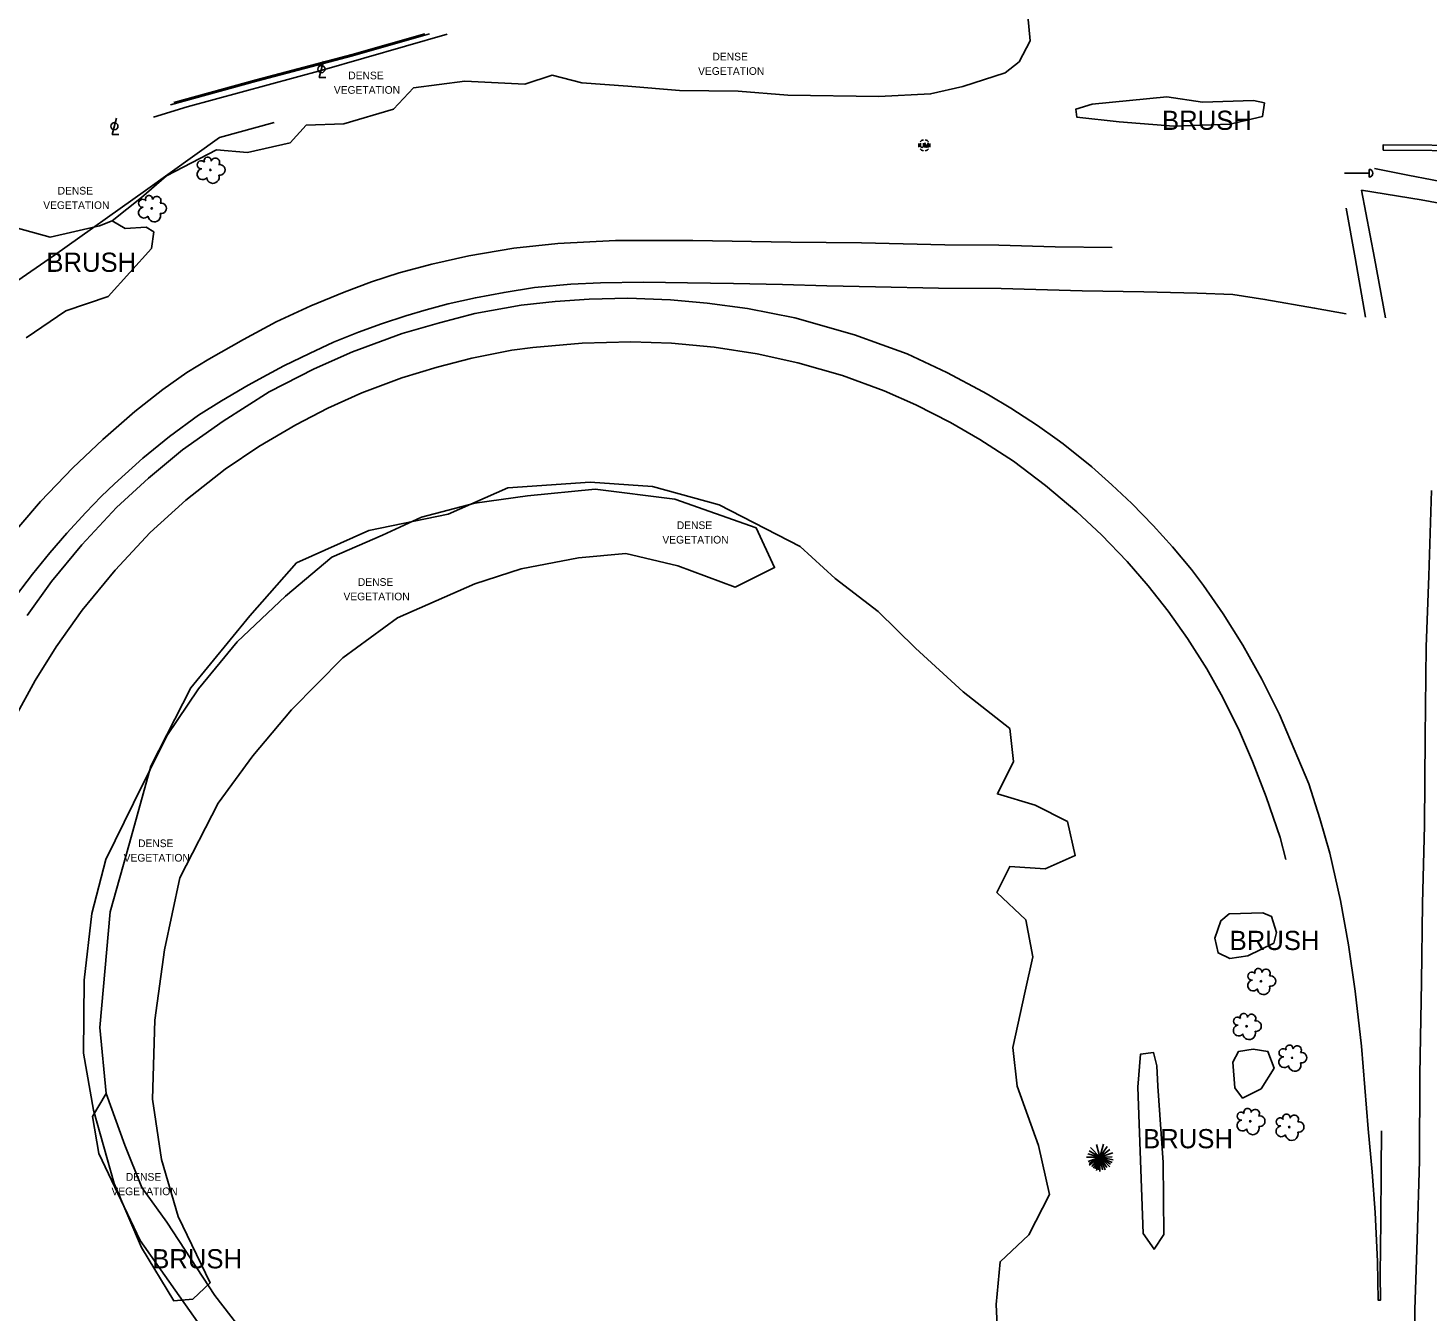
# Model space of a CAD drawing. Extents: x 2129547 to 2134906, y 657330 to 659734.
# Drawn here: x 2131974 to 2132485, y 658719 to 659188 of the extents above; entities that cross this region are included whole.
import ezdxf

# ---------------------------------------------------------------- set-up
doc = ezdxf.new("R2010")
doc.units = 0
for name, color, linetype in [('Default', 7, 'Continuous'), ('LT_X_Poles', 7, 'Continuous'), ('PM_X_Crosswalk2', 7, 'Continuous'), ('PM_X_Edge_Line', 7, 'Continuous'), ('PM_X_Lane_Line', 7, 'Continuous'), ('PM_X_Stop_Line2', 7, 'Continuous'), ('PV_X_Curb', 7, 'Continuous'), ('PV_X_Parking_Lot', 7, 'Continuous'), ('RD_X_Fence', 7, 'Continuous'), ('RD_X_Misc_Items', 7, 'Continuous'), ('SG_X_Detection', 7, 'Continuous'), ('UT_X_Unknown_Cells', 7, 'Continuous'), ('VG_X_Cells', 7, 'Continuous'), ('VG_X_Shrub_Line_Lt', 7, 'Continuous'), ('VG_X_Text', 7, 'Continuous'), ('VG_X_Tree_Line_Lt', 7, 'Continuous')]:
    doc.layers.add(name, color=color, linetype=linetype)

# ---------------------------------------------------------------- blocks, each defined once
blk = doc.blocks.new('LPOLE')
at = {"layer": 'LT_X_Poles'}
blk.add_lwpolyline([(0.01, 0.0375), (-0.01, -0.0385), (0.02, -0.0385)], dxfattribs=at)
blk.add_circle((0, 0), 0.0165, dxfattribs=at)
blk = doc.blocks.new('TREE')
at = {"layer": 'VG_X_Cells'}
blk.add_circle((0, 0), 0.00305, dxfattribs=at)
for centre, radius, start, end in [((-0.0362, -0.0197), 0.0251, 96.17219, 320.57371), ((-0.042, 0.0237), 0.0187, 39.06254, 279.54124), ((-0.0125, 0.0428), 0.0167, 354.0047, 205.97412), ((0.0232, 0.0359), 0.0197, 323.82996, 165.0376), ((0.0439, 0.0005), 0.0243, 259.14531, 101.45961), ((0.012, -0.0331), 0.029, 184.94757, 19.45715)]:
    blk.add_arc(centre, radius, start, end, dxfattribs=at)
blk = doc.blocks.new('UMH')
at = {"layer": 'UT_X_Unknown_Cells'}
for p, q in [((-0.017, 0.0104), (-0.017, -0.0059)), ((-0.0042, 0.0104), (-0.0042, -0.0059))]:
    blk.add_line(p, q, dxfattribs=at)
blk.add_lwpolyline([(0.0024, -0.01), (0.0024, 0.0104), (0.0099, -0.01), (0.0174, 0.0104), (0.0174, -0.01)], dxfattribs=at)
for centre, radius, start, end in [((0, 0), 0.0254, 160.01689, 200.03919), ((0, 0), 0.0254, 100.0806, 140.07213), ((0, 0), 0.0254, 40.05767, 80.10608), ((0, 0), 0.0254, 340.01689, 20.03919), ((0, 0), 0.0254, 220.05767, 260.04731), ((-0.0106, -0.0029), 0.00708, 205.19243, 334.80757), ((0, 0), 0.0254, 280.01144, 320.02638)]:
    blk.add_arc(centre, radius, start, end, dxfattribs=at)
blk = doc.blocks.new('ETREE')
at = {"layer": 'VG_X_Cells'}
for p, q in [((-0.0627, 0), (0, 0)), ((0, 0), (-0.056, 0.015)), ((0, 0), (-0.0545, -0.0198)), ((0, 0), (-0.0506, -0.029)), ((0, 0), (-0.0496, 0.0292)), ((0, 0), (-0.0496, -0.038)), ((0, 0), (-0.0443, 0.0443)), ((0, 0), (-0.0374, -0.044)), ((0, 0), (-0.0294, -0.051)), ((0, 0), (-0.0211, -0.0551)), ((0, 0), (-0.016, -0.0617)), ((0, 0), (-0.0157, 0.0586)), ((0, 0), (-0.0069, -0.0583)), ((0, 0), (0.016, 0.0597)), ((0, 0), (0.0337, 0.0493)), ((0, 0), (0.0464, 0.0356)), ((0, 0), (0.0602, 0.0204)), ((0, 0), (0.0573, 0.0012)), ((0, -0.0665), (0, 0)), ((0, 0), (0.0117, -0.0589)), ((0, 0), (0.0246, -0.0593)), ((0, 0), (0.0322, -0.0482)), ((0, 0), (0.0456, -0.0447)), ((0, 0), (0.0485, -0.0324)), ((0, 0), (0.0567, -0.0247)), ((0, 0), (0.0613, -0.0122))]:
    blk.add_line(p, q, dxfattribs=at)
blk = doc.blocks.new('PEDPB')
at = {"layer": 'Default'}
blk.add_line((0.0457, 0), (0, 0), dxfattribs=at)
blk.add_lwpolyline([(0.0457, -0.0071), (0.0457, -0.0071), (0.0457, 0.0071), (0.0457, 0.0071)], dxfattribs=at)
blk.add_arc((0.0457, 0), 0.00711, 270.0002, 89.9998, dxfattribs=at)

msp = doc.modelspace()

# ---------------------------------------------------------------- linework, layer by layer
at = {"layer": 'PM_X_Crosswalk2'}
for points in [[(2132534.55, 659123.31), (2132513.69, 659127.04), (2132495.2, 659130.51), (2132477.48, 659133.95), (2132465.32, 659136.32)], [(2132469.3, 659081.92), (2132465.27, 659103.71), (2132460.59, 659128.44), (2132482.25, 659124.89), (2132507.25, 659120.29), (2132536.23, 659114.67), (2132535.64, 659093.84), (2132534.49, 659067.12), (2132533.02, 659033.77)], [(2132454.94, 659121.92), (2132458.19, 659103.79), (2132462.01, 659082.12)]]:
    msp.add_lwpolyline(points, dxfattribs=at)
at = {"layer": 'PM_X_Edge_Line'}
for points in [[(2132369.6, 659107.5), (2132348.81, 659107.85), (2132328.2, 659108.38), (2132308.55, 659108.54), (2132278.14, 659109.27), (2132252.35, 659109.51), (2132216.6, 659110.05), (2132188.42, 659110.07), (2132167.35, 659109.07), (2132151.39, 659107.31), (2132134.97, 659104.51), (2132121.5, 659101.46), (2132109.53, 659098.26), (2132099.49, 659095.05), (2132089.47, 659091.31), (2132077.32, 659086.26), (2132064.72, 659080.45), (2132052.79, 659074.04), (2132040.05, 659066.77), (2132032.09, 659062.01), (2132023.36, 659055.77), (2132013.14, 659047.72), (2132001.4, 659037.49), (2131990.46, 659027.2), (2131978.75, 659014.89), (2131965.12, 658998.99)], [(2132454.96, 659083.37), (2132443.41, 659085.44), (2132425.31, 659088.59), (2132413.55, 659090.4), (2132400.61, 659090.94), (2132381.16, 659091.35), (2132358.63, 659091.73), (2132329.13, 659092.59), (2132306.24, 659092.74), (2132283.24, 659093.2), (2132265.47, 659093.58), (2132249.29, 659094.08), (2132231.52, 659094.41), (2132214.76, 659094.7), (2132198.61, 659094.91), (2132182.91, 659094.68), (2132172.12, 659094.14), (2132158.86, 659092.97), (2132147.78, 659091.16), (2132137.35, 659089.23), (2132127.37, 659086.96), (2132119.42, 659084.86), (2132111.91, 659082.68), (2132103.12, 659079.77), (2132094.69, 659076.7), (2132085.6, 659072.97), (2132076.79, 659068.94), (2132067.52, 659064.36), (2132061.35, 659061.15), (2132054.49, 659057.39), (2132044.71, 659051.65), (2132036.32, 659046.42), (2132025.72, 659038.58), (2132016, 659030.67), (2132005.66, 659021.4), (2132000.8, 659016.75), (2131995.2, 659010.86), (2131988.33, 659003.31), (2131982.16, 658996.19), (2131975.74, 658988.36), (2131967.68, 658977.75)], [(2131973.8, 658973.32), (2131982.78, 658985.7), (2131993.82, 658999.13), (2132006.37, 659012.69), (2132018.09, 659023.44), (2132030.45, 659033.71), (2132045.3, 659044.23), (2132062.09, 659054.86), (2132078.53, 659063.34), (2132092.46, 659069.49), (2132110.64, 659076.22), (2132124.25, 659080.1), (2132137.15, 659083.43), (2132154.08, 659086.47), (2132166.4, 659087.82), (2132178.85, 659088.68), (2132192.97, 659089.07), (2132208.49, 659088.52), (2132221.86, 659087.29), (2132236.56, 659085.27), (2132253.83, 659081.94), (2132275.64, 659075.71), (2132285.68, 659072.09), (2132294.87, 659068.74), (2132309.27, 659061.96), (2132322.49, 659054.92), (2132324.53, 659053.85), (2132332.64, 659048.95), (2132342.39, 659042.66), (2132349.56, 659037.55), (2132351.76, 659035.88), (2132362.16, 659027.56), (2132369.45, 659020.94), (2132376.71, 659014.23), (2132384.59, 659006.17), (2132391.62, 658998.4), (2132398.53, 658990.09), (2132402.88, 658984.23), (2132410.04, 658973.91), (2132417.25, 658962.45), (2132424.15, 658950.13), (2132430.58, 658937.17), (2132441.3, 658911.91), (2132445.33, 658899.24), (2132448.95, 658886.6), (2132452.85, 658869.37), (2132455.83, 658853.2), (2132458.2, 658836.36), (2132460.51, 658816.27), (2132463.02, 658786.06)], [(2132432.93, 658884.27), (2132430.84, 658892.3), (2132425.75, 658907.16), (2132420.8, 658920.06), (2132415.99, 658931.17), (2132410.01, 658943.38), (2132404.07, 658953.86), (2132397.07, 658964.91), (2132390.02, 658974.87), (2132382.72, 658984.2), (2132375.12, 658993.06), (2132365.71, 659002.73), (2132356.71, 659011.15), (2132345.27, 659020.76), (2132333.57, 659029.6), (2132321.35, 659037.57), (2132310.64, 659043.78), (2132298.01, 659050.21), (2132286.49, 659055.25), (2132271.25, 659060.9), (2132254.99, 659065.48), (2132240.11, 659068.8), (2132224.38, 659071.24), (2132208.88, 659072.63), (2132194.03, 659073.19), (2132176.27, 659072.71), (2132158.33, 659071.06), (2132150.61, 659070.08), (2132136.09, 659067.21), (2132123.35, 659063.95), (2132110.55, 659059.97), (2132095.9, 659054.6), (2132083.55, 659048.95), (2132071.86, 659042.93), (2132058.33, 659034.96), (2132046.08, 659026.69), (2132031.74, 659015.37), (2132018.72, 659003.66), (2132005.89, 658989.84), (2131993.94, 658975.32), (2131984.42, 658961.85), (2131976.72, 658949.61), (2131969.57, 658936.5)], [(2132467.88, 658785.31), (2132467.68, 658771.09), (2132467.55, 658752.47), (2132467.35, 658732.97), (2132467.46, 658723.56), (2132466.66, 658723.56), (2132466.35, 658737.65), (2132465.49, 658755.62), (2132464.46, 658770.41), (2132463.02, 658786.06)]]:
    msp.add_lwpolyline(points, dxfattribs=at)
at = {"layer": 'PM_X_Lane_Line'}
msp.add_lwpolyline([(2132479.46, 658662.15), (2132479.91, 658689.3), (2132480.02, 658720.13), (2132480.79, 658745.78), (2132481.72, 658774.42), (2132481.81, 658805.92), (2132482.47, 658839.62), (2132482.81, 658868.33), (2132483.47, 658896.67), (2132483.79, 658929.03), (2132484.16, 658961.85), (2132485.12, 658987.76), (2132486.03, 659018.91)], dxfattribs=at)
at = {"layer": 'PM_X_Stop_Line2'}
msp.add_lwpolyline([(2132468.48, 659143.04), (2132504.1, 659142.84), (2132504.11, 659144.81), (2132468.49, 659145.01)], close=True, dxfattribs=at)
at = {"layer": 'PV_X_Curb'}
msp.add_lwpolyline([(2132026.18, 659159.57), (2132057.53, 659168.26), (2132092.46, 659177.49), (2132119.79, 659185.24), (2132120.61, 659185.47)], dxfattribs=at)
at = {"layer": 'PV_X_Parking_Lot'}
msp.add_lwpolyline([(2132027.38, 659160.42), (2132057.4, 659168.74), (2132092.33, 659177.97), (2132118.88, 659185.5)], dxfattribs=at)
at = {"layer": 'RD_X_Fence'}
msp.add_lwpolyline([(2132063.89, 659153.18), (2132044.02, 659147.7), (2132017.02, 659128.3), (2131983.81, 659104.8), (2131958.11, 659087.15), (2131928.28, 659065.59), (2131913.76, 659055.03), (2131902.3, 659031.68), (2131886.87, 658999.73), (2131870.43, 658966.66), (2131867.28, 658959.81), (2131866.21, 658956.4), (2131857.66, 658938.59), (2131850.11, 658923.77), (2131835.3, 658892.55), (2131813.09, 658849.05), (2131807.77, 658835.77), (2131787.53, 658792.78), (2131778.55, 658773.77), (2131750.93, 658716), (2131727.2, 658667.49), (2131715.31, 658642.03), (2131710.47, 658636.49)], dxfattribs=at)
at = {"layer": 'RD_X_Misc_Items'}
msp.add_lwpolyline([(2132156.39, 659017.01), (2132137.15, 659014.24), (2132117.7, 659009.15), (2132103.4, 659002.63), (2132084.93, 658994.59), (2132068.05, 658980.35), (2132050.41, 658963.74), (2132036.36, 658946.6), (2132024.81, 658929.44), (2132012.6, 658904.93), (2132002.59, 658884.3), (2131997.41, 658864.6), (2131994.68, 658840.32), (2131994.43, 658813.68), (2131998.06, 658792.85), (2132005.57, 658766.2), (2132015.57, 658742.76), (2132027.39, 658723.32), (2132034.31, 658723.98), (2132040.54, 658729.88), (2132028.98, 658754.06), (2132022.83, 658774.96), (2132019.59, 658796.94), (2132020.42, 658825.77), (2132023.99, 658851.44), (2132029.57, 658877.59), (2132043.46, 658904.87), (2132056.14, 658922.15), (2132070.21, 658938.87), (2132088.99, 658957.9), (2132108.97, 658972.48), (2132137.16, 658984.84), (2132153.98, 658990.4), (2132174.97, 658994.41), (2132192.26, 658995.88), (2132211.15, 658991.41), (2132232.04, 658983.67), (2132246.44, 658990.78), (2132239.74, 659005.26), (2132210.12, 659015.8), (2132181.03, 659019.41)], close=True, dxfattribs=at)
at = {"layer": 'VG_X_Shrub_Line_Lt'}
for points in [[(2132402.58, 659160.61), (2132421.13, 659161.21), (2132425.13, 659160.29), (2132424.42, 659155.28), (2132412.53, 659152.58), (2132392.03, 659151.81), (2132372.11, 659153.44), (2132356.76, 659155.04), (2132356.4, 659158.02), (2132362.26, 659159.87), (2132389.5, 659162.53)], [(2132428.58, 658853.86), (2132419.11, 658849.21), (2132412.56, 658848.27), (2132408.24, 658850.24), (2132407.02, 658855.67), (2132409.24, 658861.98), (2132412.31, 658864.55), (2132424.54, 658864.9), (2132427.72, 658863.51), (2132429.59, 658857.75)], [(2132386.23, 658801.69), (2132388.16, 658773.76), (2132388.4, 658747.51), (2132384.87, 658742.16), (2132380.87, 658747.97), (2132378.95, 658801.31), (2132379.87, 658813.29), (2132384.61, 658813.94), (2132385.85, 658809.12)]]:
    msp.add_lwpolyline(points, close=True, dxfattribs=at)
for points in [[(2132004.89, 659117.32), (2132009.64, 659114.51), (2132017.22, 659114.97), (2132020.06, 659113.25), (2132019.16, 659107.24), (2132003.45, 659089.71), (2131987.99, 659084.42), (2131973.5, 659074.57)], [(2132241.57, 658637.13), (2132257.23, 658632.16), (2132263.35, 658629.08), (2132265.8, 658620.39), (2132252.28, 658614.57), (2132199.28, 658625.58), (2132164.16, 658630.46), (2132128.73, 658643.29), (2132095.7, 658655.21), (2132062.3, 658681.54), (2132042.01, 658707.06), (2132015.09, 658745.42), (2131999.97, 658777.1), (2131997.64, 658790.64), (2132002.68, 658798.92)]]:
    msp.add_lwpolyline(points, dxfattribs=at)
at = {"layer": 'VG_X_Tree_Line_Lt'}
for points in [[(2132338.46, 659196), (2132339.64, 659182.93), (2132335.63, 659175.24), (2132330.55, 659171.2), (2132315.16, 659166.23), (2132303.39, 659163.55), (2132284.51, 659162.68), (2132251.34, 659163.13), (2132233.16, 659164.63), (2132211.79, 659164.82), (2132192.91, 659166.37), (2132176.16, 659167.67), (2132165.32, 659170.36), (2132155.42, 659167.14), (2132133.49, 659168.25), (2132114.76, 659165.79), (2132107.41, 659157.98), (2132089.34, 659152.61), (2132075.62, 659152.16), (2132069.73, 659145.75), (2132054.21, 659142.23), (2132042.92, 659143.21), (2132024.63, 659133.75), (2132015.59, 659125.75), (2132004.89, 659117.32), (2132000.17, 659115.51), (2131982.24, 659111.37), (2131969.49, 659114.84)], [(2132019.9, 659155.11), (2132032.26, 659158.87), (2132081.49, 659172.27), (2132127, 659185.37)], [(2132055.99, 658707.55), (2132042.26, 658725.35), (2132024.74, 658752.02), (2132015.62, 658764.65), (2132009.41, 658780.08), (2132002.68, 658798.92), (2132000.3, 658823.07), (2132004.06, 658865.18), (2132011.2, 658890.3), (2132018.99, 658918.41), (2132033.53, 658946.92), (2132055.09, 658973.24), (2132072.14, 658992.58), (2132098.47, 659004.29), (2132127.43, 659010.23), (2132149.13, 659019.95), (2132179.2, 659021.98), (2132201.88, 659020.41), (2132226.2, 659013.74), (2132255.82, 658998.52), (2132268.52, 658986.81), (2132284.27, 658974.84), (2132297.86, 658961.47), (2132315.24, 658945.43), (2132332.31, 658932.09), (2132333.61, 658920.11), (2132327.75, 658908.25), (2132341.47, 658904.12), (2132353.3, 658898.17), (2132356.11, 658885.73), (2132345.21, 658880.88), (2132332.22, 658881.73), (2132327.55, 658872.31), (2132338.11, 658862.28), (2132340.63, 658848.84), (2132337.83, 658836.34), (2132333.42, 658815.79), (2132334.99, 658801.65), (2132342.69, 658780), (2132346.71, 658762.08), (2132339.19, 658747.38), (2132328.74, 658737.61), (2132327.28, 658721.96), (2132327.82, 658711.7)]]:
    msp.add_lwpolyline(points, dxfattribs=at)
msp.add_lwpolyline([(2132420.99, 658815.11), (2132426.43, 658814.33), (2132428.69, 658808.18), (2132423.89, 658800.71), (2132417.15, 658797.28), (2132414.37, 658801.1), (2132413.55, 658810.46), (2132415.63, 658814.26)], close=True, dxfattribs=at)

# ---------------------------------------------------------------- block references
at = {"layer": 'LT_X_Poles', "xscale": 78.74000000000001, "yscale": 78.74000000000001}
for p in [(2132081.19, 659172.62), (2132005.66, 659151.79)]:
    msp.add_blockref('LPOLE', p, dxfattribs=at)
at = {"layer": 'SG_X_Detection', "xscale": 196.85000000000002, "yscale": 196.85000000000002}
msp.add_blockref('PEDPB', (2132454.31, 659134.66), dxfattribs=at)
at = {"layer": 'UT_X_Unknown_Cells', "xscale": 78.74000000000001, "yscale": 78.74000000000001}
msp.add_blockref('UMH', (2132301.08, 659144.82), dxfattribs=at)
at = {"layer": 'VG_X_Cells', "xscale": 78.74000000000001, "yscale": 78.74000000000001}
for name, p in [('TREE', (2132040.66, 659135.83)), ('TREE', (2132019.28, 659121.8)), ('TREE', (2132423.87, 658839.93)), ('TREE', (2132418.61, 658823.5)), ('TREE', (2132435.24, 658811.99)), ('TREE', (2132419.96, 658788.84)), ('TREE', (2132434.18, 658786.74)), ('ETREE', (2132365.14, 658775.78))]:
    msp.add_blockref(name, p, dxfattribs=at)

# ---------------------------------------------------------------- texts
at = {"layer": 'VG_X_Text'}
for s, height, p in [('DENSE', 2.8, (2132223.81, 659175.78)), ('VEGETATION', 2.8, (2132218.57, 659170.51)), ('DENSE', 2.8, (2132090.97, 659168.9)), ('VEGETATION', 2.8, (2132085.72, 659163.63)), ('BRUSH', 7, (2132387.78, 659150.45)), ('DENSE', 2.8, (2131984.96, 659126.87)), ('VEGETATION', 2.8, (2131979.71, 659121.59)), ('BRUSH', 7, (2131980.84, 659098.67)), ('DENSE', 2.8, (2132210.79, 659004.85)), ('VEGETATION', 2.8, (2132205.54, 658999.58)), ('DENSE', 2.8, (2132094.48, 658984.14)), ('VEGETATION', 2.8, (2132089.23, 658978.87)), ('DENSE', 2.8, (2132014.3, 658888.83)), ('VEGETATION', 2.8, (2132009.05, 658883.56)), ('BRUSH', 7, (2132412.45, 658851.31)), ('BRUSH', 7, (2132380.88, 658779)), ('DENSE', 2.8, (2132009.84, 658767.17)), ('VEGETATION', 2.8, (2132004.6, 658761.89)), ('BRUSH', 7, (2132019.46, 658735.2))]:
    msp.add_text(s, height=height, dxfattribs=at).set_placement(p)

doc.saveas('drawing.dxf')
